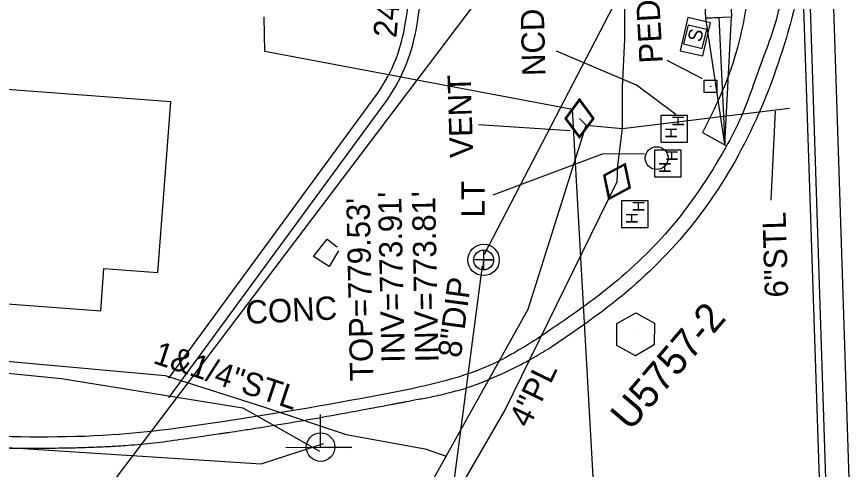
# Model space of a CAD drawing. Extents: x 1627482 to 1629573, y 760826 to 766301.
# Drawn here: x 1628315.8 to 1628458.5, y 761670.2 to 761748 of the extents above; entities that cross this region are included whole.
import ezdxf

# ---------------------------------------------------------------- set-up
doc = ezdxf.new("R2010")
doc.units = 0
for name, color, linetype in [('CTL Primary Horizontal and Vertical CELL', 7, 'Continuous'), ('CTL Primary Horizontal and Vertical Text', 7, 'Continuous'), ('Exist Building', 7, 'Continuous'), ('Exist Right of Way Line', 7, 'Continuous'), ('Exist Roads Change in Surface', 7, 'Continuous'), ('Exist Roads Curbs', 7, 'Continuous'), ('Exist Roads Curbs Text', 7, 'Continuous'), ('Exist Roads EOP', 7, 'Continuous'), ('Exist Roads EOP Other', 7, 'Continuous'), ('Exist Roads EOP Other Text', 7, 'Continuous'), ('Exist Roads EOT', 7, 'Continuous'), ('Exist Structure Minor Pipes RCP 18 Inch', 7, 'Continuous'), ('Exist Structure Minor Pipes RCP 18 Inch Invert', 7, 'Continuous'), ('Exist Utilities Gas UG Line SUE', 7, 'Continuous'), ('Exist Utilities Gas UG Line SUE Leader', 7, 'Continuous'), ('Exist Utilities Gas UG Line SUE Text', 7, 'Continuous'), ('Exist Utilities Gas Valve CELL', 7, 'Continuous'), ('Exist Utilities Gas Valve Leader', 7, 'Continuous'), ('Exist Utilities Gas Valve Text', 7, 'Continuous'), ('Exist Utilities Other Pole Located Topo CELL', 7, 'Continuous'), ('Exist Utilities Other Pole Located Topo Leader', 7, 'Continuous'), ('Exist Utilities Other Pole Located Topo Text', 7, 'Continuous'), ('Exist Utilities Other Pole Metal with Mast Arm CELL', 7, 'Continuous'), ('Exist Utilities Other Pole With Base CELL', 7, 'Continuous'), ('Exist Utilities Other Pole With Base Text', 7, 'Continuous'), ('Exist Utilities Other Traffic Signal Box CELL', 7, 'Continuous'), ('Exist Utilities Power Hand Hole CELL', 7, 'Continuous'), ('Exist Utilities Power Hand Hole Text', 7, 'Continuous'), ('Exist Utilities Power Joint Use Telephone CELL', 7, 'Continuous'), ('Exist Utilities Power UG Cable SUE', 7, 'Continuous'), ('Exist Utilities Sanitary Sewer Manhole CELL', 7, 'Continuous'), ('Exist Utilities Sanitary Sewer Manhole Text', 7, 'Continuous'), ('Exist Utilities Sanitary Sewer UG Line', 7, 'Continuous'), ('Exist Utilities Sanitary Sewer UG Line Invert Elevation', 7, 'Continuous'), ('Exist Utilities Sanitary Sewer UG Line Text', 7, 'Continuous'), ('Exist Utilities Telephone Hand Hole CELL', 7, 'Continuous'), ('Exist Utilities Telephone Hand Hole Leader', 7, 'Continuous'), ('Exist Utilities Telephone UG Cable', 7, 'Continuous')]:
    doc.layers.add(name, color=color, linetype=linetype)

# ---------------------------------------------------------------- blocks, each defined once
blk = doc.blocks.new('EXIST UTILITIES POWER JOINT USE TELEPHONE')
at = {"layer": 'Exist Utilities Power Joint Use Telephone CELL'}
blk.add_line((0, 0), (0, 0), dxfattribs=at)
blk.add_lwpolyline([(-0.1188, 0), (0.108, -0.0008), (0, -0.0004), (0, 0.1125)], dxfattribs=at)
blk.add_circle((0, 0.0001), 0.049, dxfattribs=at)
blk = doc.blocks.new('EXIST UTILITIES GAS VALVE')
at = {"layer": 'Exist Utilities Gas Valve CELL'}
blk.add_line((0, 0), (0, 0), dxfattribs=at)
blk.add_lwpolyline([(0, 0.0683), (-0.0508, 0), (0, -0.0683), (0.0508, 0), (0, 0.0683)], dxfattribs=at)
blk.add_lwpolyline([(0.0458, 0), (0, 0.0615), (-0.0458, 0), (0, -0.0615)], close=True, dxfattribs=at)

msp = doc.modelspace()

# ---------------------------------------------------------------- linework, layer by layer
at = {"layer": 'CTL Primary Horizontal and Vertical CELL'}
msp.add_line((1628422.12, 761693.43), (1628422.12, 761693.43), dxfattribs=at)
msp.add_lwpolyline([(1628418.89, 761695.3), (1628422.14, 761697.11), (1628425.39, 761695.32), (1628425.34, 761691.6), (1628422.09, 761689.71), (1628418.89, 761691.52)], close=True, dxfattribs=at)
at = {"layer": 'Exist Building'}
msp.add_lwpolyline([(1628224.63, 761705.38), (1628330.24, 761697.46), (1628330.79, 761704.74), (1628340.07, 761704.04), (1628342.27, 761733.39), (1628257.76, 761739.73), (1628258.09, 761744.12), (1628227.7, 761746.39)], close=True, dxfattribs=at)
at = {"layer": 'Exist Right of Way Line'}
msp.add_lwpolyline([(1628432.08, 761799.93), (1628146.24, 761422.3)], dxfattribs=at)
at = {"layer": 'Exist Roads Change in Surface'}
msp.add_lwpolyline([(1628371.1, 761707.77), (1628369.46, 761705.07), (1628366.81, 761706.81), (1628369.15, 761709.75), (1628370.87, 761708.45)], dxfattribs=at)
at = {"layer": 'Exist Roads Curbs'}
for p, q in [((1628341.95, 761682.54), (1628379.05, 761733.14)), ((1628406.1, 761693.24), (1628406.1, 761693.24))]:
    msp.add_line(p, q, dxfattribs=at)
for centre, radius, start, end in [((1628275.07, 761764.87), 111.01, 350.058, 1.1827), ((1628354.85, 761750.88), 30, 323.7517, 350.058)]:
    msp.add_arc(centre, radius, start, end, dxfattribs=at)
for points in [[(1628448.96, 761772.33), (1628448.46, 761759.38), (1628447.61, 761753.64), (1628446.64, 761748.89), (1628444.83, 761743.05), (1628444.15, 761741.26), (1628442.08, 761735.5), (1628440.31, 761730.88), (1628437.56, 761725.47), (1628427.83, 761711.35), (1628416.86, 761700.95), (1628406.1, 761693.24)], [(1628406.1, 761693.24), (1628398.19, 761688.61), (1628380.21, 761683.39), (1628351.52, 761678.46), (1628332.16, 761676.14), (1628307.15, 761676.02), (1628278.21, 761676.97), (1628240.95, 761678.46), (1628208.08, 761679.92)]]:
    msp.add_spline(points, degree=3, dxfattribs=at)
at = {"layer": 'Exist Roads EOP'}
msp.add_line((1628407.32, 761691.02), (1628407.35, 761690.99), dxfattribs=at)
msp.add_spline([(1628451.42, 761772.47), (1628451.04, 761759.12), (1628446.99, 761741.12), (1628439.74, 761724.14), (1628429.71, 761709.68), (1628417.3, 761698.07), (1628407.32, 761691.02)], degree=3, dxfattribs=at)
at = {"layer": 'Exist Roads EOP Other'}
for p, q in [((1628341.94, 761685.92), (1628377.44, 761734.33)), ((1628433.6, 761728.12), (1628437.74, 761725.8))]:
    msp.add_line(p, q, dxfattribs=at)
msp.add_lwpolyline([(1628431.1, 761747.83), (1628429.78, 761742.15), (1628433.69, 761741.26), (1628435.02, 761746.93)], close=True, dxfattribs=at)
for centre, radius, start, end in [((1628275.07, 761764.87), 109.01, 350.058, 1.1827), ((1628354.85, 761750.88), 28, 323.7517, 350.058)]:
    msp.add_arc(centre, radius, start, end, dxfattribs=at)
for points in [[(1628439.75, 761778.12), (1628441.05, 761771.89), (1628442.4, 761762.28), (1628441.45, 761751.54), (1628439.06, 761740.73), (1628436.73, 761734.53), (1628433.6, 761728.12)], [(1628394.81, 761684.81), (1628400.44, 761687.25), (1628404.24, 761689.24), (1628407.32, 761691.02)]]:
    msp.add_spline(points, degree=3, dxfattribs=at)
msp.add_open_spline([(1628394.81, 761684.81), (1628393.12, 761684.17), (1628391.4, 761683.67), (1628387.56, 761682.73), (1628385.43, 761682.33), (1628382.83, 761681.85), (1628382.31, 761681.75), (1628381.54, 761681.61), (1628381.16, 761681.54), (1628380.77, 761681.46), (1628380.52, 761681.42), (1628380.39, 761681.39), (1628379.23, 761681.17), (1628376.14, 761680.58), (1628368.93, 761679.24), (1628362.74, 761678.18), (1628356.52, 761677.19), (1628354.45, 761676.87), (1628352.11, 761676.52), (1628351.85, 761676.48), (1628351.33, 761676.41), (1628350.56, 761676.3), (1628348.75, 761676.03), (1628347.19, 761675.8), (1628341.99, 761675.05), (1628337.8, 761674.51), (1628333.01, 761674.19), (1628332.47, 761674.16), (1628331.42, 761674.1), (1628329.84, 761674.03), (1628326.15, 761673.89), (1628322.99, 761673.84), (1628316.67, 761673.8), (1628312.47, 761673.87), (1628307.75, 761674), (1628307.22, 761674.02), (1628306.18, 761674.05), (1628304.61, 761674.1), (1628300.96, 761674.21), (1628293.64, 761674.43), (1628287.37, 761674.63), (1628282.14, 761674.82), (1628281.1, 761674.85), (1628279, 761674.93), (1628277.96, 761674.98), (1628274.83, 761675.1), (1628268.56, 761675.34), (1628258.12, 761675.74), (1628249.76, 761676.07), (1628243.49, 761676.34), (1628241.4, 761676.43), (1628237.22, 761676.62), (1628226.78, 761677.08), (1628216.34, 761677.55), (1628207.99, 761677.92)], degree=3, dxfattribs=at)
at = {"layer": 'Exist Roads EOT'}
for p, q in [((1628473.68, 761214.67), (1628455.37, 761774.37)), ((1628457.9, 761574.84), (1628451.46, 761771.71))]:
    msp.add_line(p, q, dxfattribs=at)
at = {"layer": 'Exist Structure Minor Pipes RCP 18 Inch'}
for p, q in [((1628456.79, 761575.18), (1628450.29, 761772.67)), ((1628421.4, 761552.58), (1628411.26, 761732.07))]:
    msp.add_line(p, q, dxfattribs=at)
at = {"layer": 'Exist Structure Minor Pipes RCP 18 Inch Invert'}
msp.add_lwpolyline([(1628411.26, 761732.07), (1628358.44, 761741.99), (1628358.32, 761747.98)], dxfattribs=at)
at = {"layer": 'Exist Utilities Gas UG Line SUE'}
for points in [[(1628420.26, 761744.11), (1628420.44, 761782.06), (1628417.81, 761791.87), (1628415.7, 761838.78), (1628414.52, 761869.09), (1628413.48, 761897.67), (1628412.77, 761938.43), (1628412.4, 761972.38), (1628412.53, 761994.78), (1628412.28, 762024.83), (1628413.8, 762067.91), (1628415.6, 762097.38)], [(1628418.94, 761719.68), (1628419.08, 761722.44), (1628419.89, 761728.8), (1628419.9, 761735.89), (1628420.26, 761744.11)], [(1628419.89, 761728.8), (1628448.56, 761732.3)], [(1628412.49, 761730.51), (1628413.63, 761729.38)], [(1628107.21, 761398.96), (1628106.54, 761402.67), (1628116.88, 761405.77), (1628151.1, 761408.38), (1628180.43, 761414.9), (1628192.91, 761420.7), (1628204.95, 761428.91), (1628225.97, 761449.06), (1628243.25, 761470.03), (1628269.14, 761502.92), (1628294.62, 761536.12), (1628323.09, 761572.16), (1628354.96, 761616.04), (1628378.95, 761653.33), (1628389.59, 761672.5), (1628403.67, 761697.73), (1628413.63, 761729.38), (1628419.89, 761728.8)], [(1628074.03, 761404.42), (1628082.95, 761406.14), (1628117.81, 761411.15), (1628150.65, 761410.46), (1628162.9, 761405.76), (1628195.7, 761416.48), (1628218.76, 761434.91), (1628247.28, 761466.97), (1628273.32, 761500.41), (1628299.4, 761533.69), (1628331.06, 761576.43), (1628354.05, 761607.59), (1628380.38, 761646.98), (1628399.62, 761680.21), (1628418.94, 761719.68)], [(1628274.27, 761693.39), (1628302.63, 761689.87), (1628341.31, 761686.38), (1628358.37, 761680.89), (1628372.42, 761676.2)], [(1628372.42, 761676.2), (1628385.98, 761673.78), (1628389.59, 761672.5)]]:
    msp.add_lwpolyline(points, dxfattribs=at)
at = {"layer": 'Exist Utilities Gas UG Line SUE Leader'}
msp.add_line((1628446.1, 761731.78), (1628445.36, 761716.5), dxfattribs=at)
at = {"layer": 'Exist Utilities Gas Valve Leader'}
msp.add_line((1628410.87, 761728.36), (1628395.15, 761729.4), dxfattribs=at)
at = {"layer": 'Exist Utilities Other Pole Located Topo CELL'}
msp.add_circle((1628425.75, 761723.69), 1.96, dxfattribs=at)
at = {"layer": 'Exist Utilities Other Pole Located Topo Leader'}
msp.add_lwpolyline([(1628423.67, 761724.45), (1628416.37, 761724.38), (1628397.61, 761717.33)], dxfattribs=at)
at = {"layer": 'Exist Utilities Other Pole Metal with Mast Arm CELL'}
msp.add_lwpolyline([(1628438.41, 761752.37), (1628438.62, 761747.93), (1628434.2, 761747.72), (1628433.99, 761752.16)], close=True, dxfattribs=at)
msp.add_lwpolyline([(1628437.43, 761726.12), (1628434.2, 761747.72), (1628436.4, 761747.83), (1628437.43, 761726.12), (1628438.62, 761747.93)], dxfattribs=at)
at = {"layer": 'Exist Utilities Other Pole With Base CELL'}
msp.add_line((1628435.02, 761736.02), (1628435.02, 761736.02), dxfattribs=at)
msp.add_lwpolyline([(1628433.93, 761737.1), (1628436.09, 761737.1), (1628436.09, 761734.94), (1628433.93, 761734.94), (1628433.93, 761737.1)], dxfattribs=at)
msp.add_circle((1628435.02, 761736.02), 0.0283, dxfattribs=at)
at = {"layer": 'Exist Utilities Other Pole With Base Text'}
msp.add_line((1628433.61, 761737.3), (1628427.57, 761740.45), dxfattribs=at)
at = {"layer": 'Exist Utilities Other Traffic Signal Box CELL'}
msp.add_line((1628432.36, 761744.54), (1628432.36, 761744.54), dxfattribs=at)
msp.add_lwpolyline([(1628433.59, 761742.55), (1628434.34, 761745.77), (1628431.13, 761746.52), (1628430.37, 761743.31), (1628433.59, 761742.55)], dxfattribs=at)
at = {"layer": 'Exist Utilities Power Hand Hole CELL'}
for p, q in [((1628428.86, 761728.8), (1628428.86, 761728.8)), ((1628427.79, 761722.85), (1628427.79, 761722.85))]:
    msp.add_line(p, q, dxfattribs=at)
for points in [[(1628431.04, 761726.44), (1628431.04, 761731.04), (1628426.44, 761731.04), (1628426.44, 761726.44), (1628431.04, 761726.44)], [(1628429.97, 761720.49), (1628429.97, 761725.09), (1628425.37, 761725.09), (1628425.37, 761720.49), (1628429.97, 761720.49)]]:
    msp.add_lwpolyline(points, dxfattribs=at)
at = {"layer": 'Exist Utilities Power Hand Hole Text'}
msp.add_lwpolyline([(1628429.04, 761731.19), (1628422.3, 761736.2), (1628408.56, 761742.06)], dxfattribs=at)
at = {"layer": 'Exist Utilities Power UG Cable SUE'}
msp.add_lwpolyline([(1628271.93, 761690.95), (1628323.52, 761685.83), (1628354.65, 761680.81), (1628367.79, 761673.35)], dxfattribs=at)
at = {"layer": 'Exist Utilities Sanitary Sewer Manhole CELL'}
msp.add_lwpolyline([(1628396.01, 761707.91), (1628396.01, 761704.49), (1628396.01, 761706.2), (1628397.73, 761706.2), (1628394.3, 761706.2)], dxfattribs=at)
for radius in [2.69, 1.71]:
    msp.add_circle((1628396.01, 761706.2), radius, dxfattribs=at)
at = {"layer": 'Exist Utilities Sanitary Sewer UG Line'}
for p, q in [((1628396.19, 761707.18), (1628440.34, 761792.32)), ((1628387.62, 761643.18), (1628395.84, 761705.21))]:
    msp.add_line(p, q, dxfattribs=at)
at = {"layer": 'Exist Utilities Telephone Hand Hole CELL'}
for p, q in [((1628424.3, 761716.36), (1628419.72, 761716.36)), ((1628419.72, 761716.36), (1628419.72, 761711.78)), ((1628424.3, 761711.78), (1628424.3, 761716.36)), ((1628422.01, 761714.07), (1628422.01, 761714.07)), ((1628419.72, 761711.78), (1628424.3, 761711.78))]:
    msp.add_line(p, q, dxfattribs=at)
at = {"layer": 'Exist Utilities Telephone Hand Hole Leader'}
msp.add_line((1628419.11, 761709.87), (1628419.11, 761709.87), dxfattribs=at)
at = {"layer": 'Exist Utilities Telephone UG Cable'}
msp.add_lwpolyline([(1628259.03, 761677.51), (1628357.8, 761671.16), (1628368.59, 761674.66)], dxfattribs=at)

# ---------------------------------------------------------------- block references
at = {"layer": 'Exist Utilities Gas Valve CELL', "xscale": 50, "yscale": 50}
msp.add_blockref('EXIST UTILITIES GAS VALVE', (1628412.49, 761730.51), dxfattribs=at)
at = {"layer": 'Exist Utilities Gas Valve CELL', "xscale": 50, "yscale": 50.00000000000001, "rotation": -25.038010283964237}
msp.add_blockref('EXIST UTILITIES GAS VALVE', (1628418.94, 761719.68), dxfattribs=at)
at = {"layer": 'Exist Utilities Power Joint Use Telephone CELL', "xscale": 50, "yscale": 50}
msp.add_blockref('EXIST UTILITIES POWER JOINT USE TELEPHONE', (1628368, 761674.05), dxfattribs=at)

# ---------------------------------------------------------------- texts
at = {"layer": 'CTL Primary Horizontal and Vertical Text'}
msp.add_text('U5757-2', height=5, rotation=49.4659, dxfattribs=at).set_placement((1628421.2, 761676.64))
at = {"layer": 'Exist Roads Curbs Text'}
msp.add_text('24"C&G', height=4, rotation=84.6374, dxfattribs=at).set_placement((1628381.01, 761744.26))
at = {"layer": 'Exist Roads EOP Other Text'}
msp.add_text('CONC', height=4, rotation=2.9369, dxfattribs=at).set_placement((1628355.21, 761695.2))
at = {"layer": 'Exist Utilities Gas UG Line SUE Text'}
for s, rotation, p in [('6"STL', 91.7247, (1628448.34, 761699.81)), ('1&1/4"STL', 341.5459, (1628339.03, 761688.53)), ('4"PL', 63.9152, (1628403.78, 761677.17))]:
    msp.add_text(s, height=4, rotation=rotation, dxfattribs=at).set_placement(p)
at = {"layer": 'Exist Utilities Gas Valve Text'}
msp.add_text('VENT', height=4, rotation=91.7247, dxfattribs=at).set_placement((1628394.22, 761723.82))
at = {"layer": 'Exist Utilities Other Pole Located Topo Text'}
msp.add_text('LT', height=4, rotation=90, dxfattribs=at).set_placement((1628396.18, 761713.51))
at = {"layer": 'Exist Utilities Other Pole With Base Text'}
msp.add_text('PED', height=4, rotation=93.0814, dxfattribs=at).set_placement((1628426.79, 761740.08))
at = {"layer": 'Exist Utilities Other Traffic Signal Box CELL'}
msp.add_text('S', height=2.38, rotation=76.7871, dxfattribs=at).set_placement((1628433.34, 761743.51))
at = {"layer": 'Exist Utilities Power Hand Hole CELL'}
for p in [(1628430.46, 761729.12), (1628429.24, 761727.07), (1628429.38, 761723.17), (1628428.17, 761721.12)]:
    msp.add_text('H', height=2, rotation=90, dxfattribs=at).set_placement(p)
at = {"layer": 'Exist Utilities Power Hand Hole Text'}
msp.add_text('NCDOT', height=4, rotation=91.5062, dxfattribs=at).set_placement((1628406.66, 761737.84))
at = {"layer": 'Exist Utilities Sanitary Sewer Manhole Text'}
msp.add_text("TOP=779.53'", height=4, rotation=91.2053, dxfattribs=at).set_placement((1628377.08, 761685.44))
at = {"layer": 'Exist Utilities Sanitary Sewer UG Line Invert Elevation'}
for s, p in [("INV=773.91'", (1628382.47, 761688.57)), ("INV=773.81'", (1628388.28, 761688.64))]:
    msp.add_text(s, height=4, rotation=91.2053, dxfattribs=at).set_placement(p)
at = {"layer": 'Exist Utilities Sanitary Sewer UG Line Text'}
msp.add_text('8"DIP', height=4, rotation=82.4514, dxfattribs=at).set_placement((1628392.09, 761689.27))
at = {"layer": 'Exist Utilities Telephone Hand Hole CELL'}
for p in [(1628423.65, 761714.46), (1628422.48, 761712.4)]:
    msp.add_text('H', height=2, rotation=90, dxfattribs=at).set_placement(p)

doc.saveas('drawing.dxf')
